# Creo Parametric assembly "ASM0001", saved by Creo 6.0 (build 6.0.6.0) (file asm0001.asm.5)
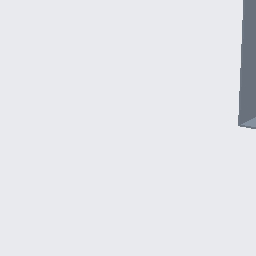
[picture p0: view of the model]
Units: Inch lbm Second (Pro/E Default); INCH, POUND, SECS

Created from: INLBS_ASM_DESIGN.ASM

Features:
  1. datum plane "ASM_RIGHT"
  2. datum plane "ASM_TOP"
  3. datum plane "ASM_FRONT"
  4. coordinate system
  5. component "PRT0001"
  6. component "LEFT"
  7. coordinate system
  8. component "BACK"
  9. component "PRT0002"
  10. component "RIGHT"

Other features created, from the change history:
  component "BACK.PRT"
  component "RIGHT.PRT"
  component "PRT0002.PRT"

Other named items: ACS4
